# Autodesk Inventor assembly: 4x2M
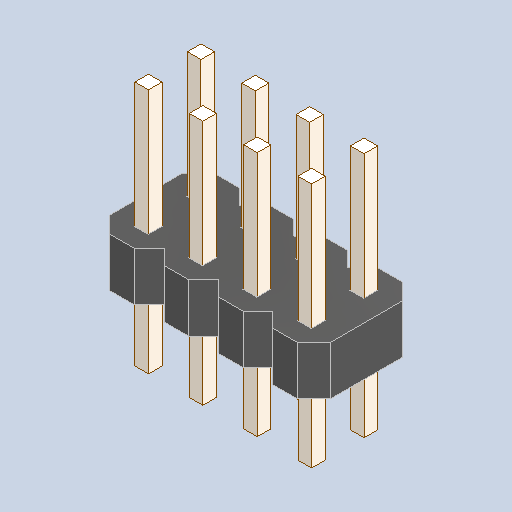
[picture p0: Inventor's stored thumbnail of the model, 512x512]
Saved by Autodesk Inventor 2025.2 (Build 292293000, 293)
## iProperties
Created: 2025-04
Part Number: 4x2M
Description: PART--DESC
Document SubType Name: Assembly
Designer: BennF
Author: BennF
Revision Number: NONE
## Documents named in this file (3)
- C:\Users\BennF\Nextcloud\Benutzer\CNC JarBeRi\existing parts\Electronics\RepRap A4988 Shied (USE WITHOUT ARDUINO)\reprap-a4988-1.snapshot.1\RepRap\RepRap\4x2M.iam
- C:\Users\BennF\Nextcloud\Benutzer\CNC JarBeRi\existing parts\Electronics\RepRap A4988 Shied (USE WITHOUT ARDUINO)\reprap-a4988-1.snapshot.1\RepRap\RepRap\4x2M Geometry.ipt
- C:\Users\BennF\Nextcloud\Benutzer\CNC JarBeRi\existing parts\Electronics\RepRap A4988 Shied (USE WITHOUT ARDUINO)\reprap-a4988-1.snapshot.1\RepRap\RepRap\pin8.ipt
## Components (2 placed, 2 different names)
1. 4x2M Geometry
2. pin8
